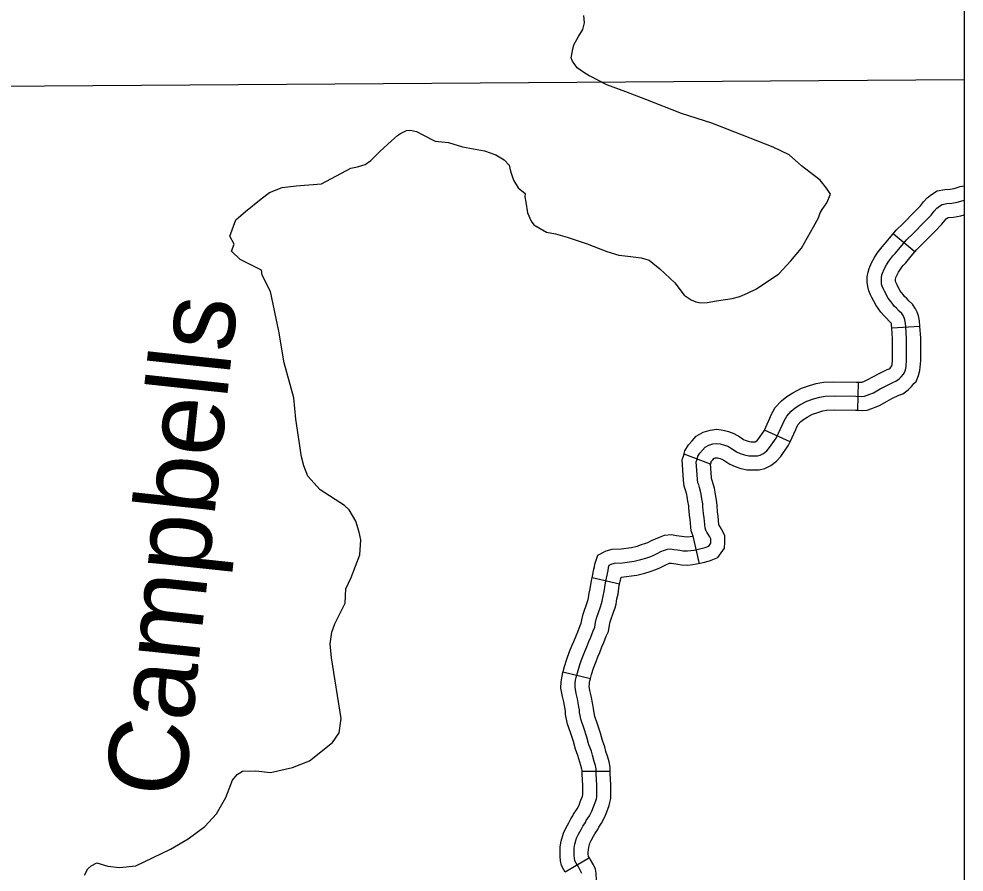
# Model space of a CAD drawing. Extents: x 1377389 to 1380723, y 1168351 to 1170484.
# Drawn here: x 1379747.5 to 1379848, y 1168972.1 to 1169062.8 of the extents above; entities that cross this region are included whole.
import ezdxf

# ---------------------------------------------------------------- set-up
doc = ezdxf.new("R2010")
doc.units = 0
doc.layers.add('B_Fill', color=7, linetype='Continuous')
doc.layers.add('B_Text', color=7, linetype='Continuous')

msp = doc.modelspace()

# ---------------------------------------------------------------- linework, layer by layer
at = {"layer": 'B_Fill'}
for p, q in [((1379842.8, 1169038.05), (1379840.5, 1169039.97)), ((1379843.34, 1169030.11), (1379840.35, 1169029.94)), ((1379836.72, 1169021.19), (1379836.8, 1169024.18)), ((1379829.52, 1169017.83), (1379826.8, 1169019.09)), ((1379821.05, 1169015.47), (1379818.24, 1169016.51)), ((1379819.87, 1169004.87), (1379819.2, 1169007.8)), ((1379811.39, 1169002.71), (1379808.46, 1169003.36)), ((1379808.28, 1168992.64), (1379805.36, 1168993.33)), ((1379810.4, 1168982.75), (1379807.4, 1168982.75)), ((1379808.19, 1168973.58), (1379805.6, 1168972.07))]:
    msp.add_line(p, q, dxfattribs=at)
for points in [[(1379809, 1169056.35), (1379808.4, 1169056.64), (1379808.16, 1169056.75), (1379807.58, 1169057.12), (1379806.89, 1169057.63), (1379806.36, 1169058.32), (1379806.22, 1169058.69), (1379806.36, 1169059.41), (1379806.52, 1169060.07), (1379807.02, 1169060.95), (1379807.47, 1169061.7), (1379807.66, 1169062.41), (1379807.58, 1169063.19)], [(1379745.02, 1169055.65), (1379848.03, 1169056.39)], [(1379782.85, 1169003.41), (1379783.75, 1169005.83), (1379783.85, 1169007.41), (1379783.68, 1169008.24), (1379783.32, 1169009.39), (1379782.61, 1169010.59), (1379782.12, 1169011.05), (1379779.54, 1169012.73), (1379778.23, 1169014.18), (1379777.81, 1169015.28), (1379777.55, 1169016.25), (1379776.96, 1169020.23), (1379776.73, 1169022.53), (1379775.7, 1169026.23), (1379775.13, 1169029.59), (1379774.27, 1169033.82), (1379773.36, 1169035.57), (1379773.3, 1169036.1), (1379771.03, 1169037.23), (1379770.12, 1169038.1), (1379770.39, 1169038.85), (1379769.93, 1169039.72), (1379770.55, 1169041.44), (1379771.6, 1169042.35), (1379773.27, 1169043.69), (1379774.13, 1169044.36), (1379775.48, 1169044.88), (1379777, 1169045.08), (1379779.67, 1169045.27), (1379782.81, 1169046.94), (1379783.5, 1169047.1), (1379784.33, 1169047.34), (1379784.93, 1169047.75), (1379785.87, 1169048.72), (1379787.13, 1169049.86), (1379787.76, 1169050.42), (1379788.09, 1169050.64), (1379788.72, 1169050.94), (1379789.14, 1169050.99), (1379789.77, 1169050.85), (1379790.47, 1169050.5), (1379791.77, 1169049.81), (1379793.19, 1169049.66), (1379794.67, 1169049.22), (1379797.01, 1169048.8), (1379798.21, 1169048.37), (1379799.12, 1169047.82), (1379799.63, 1169047.26), (1379799.79, 1169046.64), (1379800.11, 1169045.66), (1379800.59, 1169044.86), (1379801.33, 1169044.25), (1379801.31, 1169043.9), (1379801.43, 1169043.31), (1379801.6, 1169042.2), (1379801.97, 1169041.3), (1379802.26, 1169040.93), (1379802.95, 1169040.53), (1379803.62, 1169040.15), (1379804.58, 1169039.94), (1379805.8, 1169039.62), (1379807.95, 1169038.88), (1379810.02, 1169038.08), (1379811.32, 1169037.68), (1379812.28, 1169037.58), (1379813.69, 1169037.39), (1379814.54, 1169037.15), (1379814.94, 1169036.83), (1379815.68, 1169036.25), (1379817.25, 1169034.73), (1379818.26, 1169033.43), (1379819, 1169032.92), (1379819.51, 1169032.74), (1379819.99, 1169032.6), (1379820.69, 1169032.67), (1379821.68, 1169032.83), (1379823.36, 1169033.08), (1379824.19, 1169033.29), (1379825.01, 1169033.64), (1379825.94, 1169034.12), (1379828.33, 1169035.71), (1379829.61, 1169037.07), (1379830.74, 1169038.45), (1379832.02, 1169040.69), (1379832.53, 1169041.67), (1379832.74, 1169042.18), (1379832.95, 1169042.55), (1379833.43, 1169043.27), (1379833.83, 1169044.17), (1379833.41, 1169044.81), (1379832.71, 1169045.66), (1379832.13, 1169046.14), (1379830.75, 1169047.2), (1379829.41, 1169048.36), (1379827.73, 1169049.17), (1379821.21, 1169051.72), (1379817.97, 1169052.76), (1379814.17, 1169054.25), (1379812.04, 1169055.05), (1379810.02, 1169055.82), (1379809, 1169056.35)], [(1379840.5, 1169039.97), (1379840.8, 1169040.33), (1379841.54, 1169041.06), (1379842.75, 1169042.29), (1379843.38, 1169042.94), (1379843.7, 1169043.35), (1379844.09, 1169043.77), (1379844.55, 1169044.15), (1379845.18, 1169044.52), (1379846, 1169044.67), (1379846.55, 1169044.7), (1379846.96, 1169044.78), (1379847.6, 1169044.98), (1379848.03, 1169045.05)], [(1379841.81, 1169030.47), (1379841.74, 1169030.81), (1379841.65, 1169031.03), (1379841.55, 1169031.26), (1379841.41, 1169031.49), (1379841.12, 1169031.72), (1379840.86, 1169032.04), (1379840.61, 1169032.27), (1379840.37, 1169032.57), (1379839.95, 1169033.13), (1379839.56, 1169033.85), (1379839.45, 1169034.08), (1379839.33, 1169034.38), (1379839.26, 1169034.62), (1379839.24, 1169034.87), (1379839.24, 1169035.26), (1379839.3, 1169035.58), (1379839.35, 1169035.79), (1379839.52, 1169036.21), (1379839.79, 1169036.67), (1379840.03, 1169037.05), (1379840.23, 1169037.32), (1379840.46, 1169037.6), (1379840.7, 1169037.86), (1379841.27, 1169038.55), (1379841.9, 1169039.31), (1379842.6, 1169039.99), (1379843.83, 1169041.24), (1379844.52, 1169041.96), (1379844.84, 1169042.37), (1379845.12, 1169042.67), (1379845.42, 1169042.91), (1379845.71, 1169043.09), (1379846.19, 1169043.18), (1379846.73, 1169043.21), (1379847.31, 1169043.32), (1379847.95, 1169043.51), (1379848.03, 1169043.53)], [(1379842.8, 1169038.05), (1379843, 1169038.29), (1379843.66, 1169038.93), (1379844.91, 1169040.2), (1379845.66, 1169040.98), (1379845.97, 1169041.39), (1379846.14, 1169041.57), (1379846.26, 1169041.67), (1379846.37, 1169041.69), (1379846.92, 1169041.72), (1379847.67, 1169041.86), (1379848.03, 1169041.97)], [(1379840.35, 1169029.94), (1379840.35, 1169029.94), (1379840.32, 1169030.25), (1379840.3, 1169030.38), (1379840.27, 1169030.45), (1379840.25, 1169030.5), (1379840.07, 1169030.65), (1379839.77, 1169031), (1379839.52, 1169031.24), (1379839.19, 1169031.64), (1379838.68, 1169032.32), (1379838.22, 1169033.18), (1379838.08, 1169033.48), (1379837.91, 1169033.89), (1379837.78, 1169034.36), (1379837.74, 1169034.82), (1379837.74, 1169035.38), (1379837.83, 1169035.88), (1379837.92, 1169036.26), (1379838.18, 1169036.87), (1379838.5, 1169037.44), (1379838.8, 1169037.9), (1379839.04, 1169038.23), (1379839.32, 1169038.58), (1379839.57, 1169038.85), (1379840.11, 1169039.51), (1379840.5, 1169039.97)], [(1379843.34, 1169030.11), (1379843.34, 1169030.15), (1379843.3, 1169030.69), (1379843.18, 1169031.23), (1379843.03, 1169031.62), (1379842.87, 1169031.97), (1379842.55, 1169032.49), (1379842.18, 1169032.79), (1379841.95, 1169033.07), (1379841.71, 1169033.3), (1379841.55, 1169033.49), (1379841.21, 1169033.94), (1379840.9, 1169034.52), (1379840.83, 1169034.68), (1379840.75, 1169034.87), (1379840.75, 1169034.89), (1379840.74, 1169034.92), (1379840.74, 1169035.13), (1379840.77, 1169035.27), (1379840.78, 1169035.31), (1379840.87, 1169035.54), (1379841.07, 1169035.89), (1379841.27, 1169036.21), (1379841.42, 1169036.4), (1379841.59, 1169036.61), (1379841.83, 1169036.88), (1379842.42, 1169037.59), (1379842.8, 1169038.05)], [(1379810.17, 1169004.15), (1379810.21, 1169004.48), (1379810.29, 1169004.73), (1379810.5, 1169004.83), (1379810.83, 1169004.92), (1379811.7, 1169004.96), (1379812.93, 1169005.13), (1379813.65, 1169005.3), (1379814.17, 1169005.47), (1379814.71, 1169005.65), (1379815.04, 1169005.79), (1379815.45, 1169006), (1379815.78, 1169006.15), (1379816.17, 1169006.31), (1379816.5, 1169006.43), (1379816.84, 1169006.46), (1379817.17, 1169006.39), (1379817.54, 1169006.34), (1379817.79, 1169006.31), (1379818.12, 1169006.25), (1379818.6, 1169006.24), (1379818.98, 1169006.27), (1379819.3, 1169006.32), (1379819.65, 1169006.39), (1379820.5, 1169006.59), (1379820.87, 1169006.75), (1379821.08, 1169007.04), (1379821.09, 1169007.24), (1379821.09, 1169007.5), (1379820.99, 1169007.71), (1379820.8, 1169008), (1379820.65, 1169008.24), (1379820.57, 1169008.44), (1379820.48, 1169008.7), (1379820.37, 1169009.76), (1379820.3, 1169010.21), (1379820.25, 1169010.92), (1379820.23, 1169011.23), (1379820.13, 1169011.76), (1379820.06, 1169012.25), (1379820, 1169012.57), (1379819.88, 1169012.98), (1379819.81, 1169013.26), (1379819.72, 1169013.47), (1379819.69, 1169013.87), (1379819.55, 1169015.72), (1379819.67, 1169016.06), (1379819.72, 1169016.32), (1379819.92, 1169016.62), (1379820.2, 1169016.94), (1379820.5, 1169017.25), (1379820.87, 1169017.48), (1379821.31, 1169017.61), (1379821.73, 1169017.66), (1379822.1, 1169017.61), (1379822.54, 1169017.48), (1379822.91, 1169017.36), (1379823.36, 1169017.08), (1379823.84, 1169016.78), (1379824.21, 1169016.6), (1379824.68, 1169016.46), (1379825.14, 1169016.36), (1379825.67, 1169016.34), (1379826.04, 1169016.36), (1379826.35, 1169016.43), (1379826.69, 1169016.58), (1379827.06, 1169016.88), (1379827.35, 1169017.22), (1379828.06, 1169018.24), (1379828.76, 1169019.75), (1379828.88, 1169020.07), (1379829.17, 1169020.58), (1379829.64, 1169021.09), (1379830.06, 1169021.44), (1379830.57, 1169021.76), (1379831.31, 1169022.16), (1379832.03, 1169022.39), (1379832.67, 1169022.59), (1379833.25, 1169022.69), (1379834.2, 1169022.73), (1379836.52, 1169022.69), (1379837.15, 1169022.67), (1379837.43, 1169022.69), (1379837.71, 1169022.78), (1379838.01, 1169022.9), (1379838.4, 1169023.06), (1379839.12, 1169023.47), (1379839.68, 1169023.77), (1379840.47, 1169024.15), (1379840.77, 1169024.28), (1379841.12, 1169024.52), (1379841.35, 1169024.75), (1379841.58, 1169025.03), (1379841.67, 1169025.12), (1379841.78, 1169025.37), (1379841.85, 1169025.65), (1379841.86, 1169025.88), (1379841.92, 1169026.53), (1379841.92, 1169028.83), (1379841.85, 1169030.05), (1379841.81, 1169030.47)], [(1379836.72, 1169021.19), (1379837.18, 1169021.17), (1379837.71, 1169021.21), (1379838.22, 1169021.37), (1379838.58, 1169021.52), (1379839.05, 1169021.71), (1379839.84, 1169022.15), (1379840.36, 1169022.43), (1379841.09, 1169022.78), (1379841.5, 1169022.95), (1379842.09, 1169023.37), (1379842.47, 1169023.75), (1379842.7, 1169024.03), (1379842.93, 1169024.26), (1379843.2, 1169024.89), (1379843.33, 1169025.41), (1379843.36, 1169025.76), (1379843.42, 1169026.47), (1379843.42, 1169028.88), (1379843.34, 1169030.11)], [(1379836.8, 1169024.18), (1379837.12, 1169024.18), (1379837.16, 1169024.18), (1379837.2, 1169024.19), (1379837.44, 1169024.29), (1379837.74, 1169024.41), (1379838.4, 1169024.78), (1379839, 1169025.1), (1379839.86, 1169025.52), (1379840.05, 1169025.6), (1379840.16, 1169025.68), (1379840.24, 1169025.76), (1379840.36, 1169025.91), (1379840.37, 1169026), (1379840.42, 1169026.59), (1379840.42, 1169028.79), (1379840.35, 1169029.94)], [(1379826.8, 1169019.09), (1379827.38, 1169020.34), (1379827.52, 1169020.71), (1379827.94, 1169021.47), (1379828.61, 1169022.18), (1379829.18, 1169022.66), (1379829.82, 1169023.05), (1379830.72, 1169023.55), (1379831.59, 1169023.82), (1379832.31, 1169024.05), (1379833.08, 1169024.19), (1379834.18, 1169024.23), (1379836.55, 1169024.19), (1379836.8, 1169024.18)], [(1379829.52, 1169017.83), (1379830.14, 1169019.16), (1379830.25, 1169019.43), (1379830.39, 1169019.69), (1379830.67, 1169020), (1379830.94, 1169020.22), (1379831.33, 1169020.46), (1379831.9, 1169020.78), (1379832.48, 1169020.96), (1379833.02, 1169021.13), (1379833.41, 1169021.2), (1379834.21, 1169021.23), (1379836.48, 1169021.19), (1379836.72, 1169021.19)], [(1379818.22, 1169016.46), (1379818.31, 1169016.89), (1379818.72, 1169017.53), (1379819.09, 1169017.95), (1379819.54, 1169018.42), (1379820.26, 1169018.87), (1379821.01, 1169019.08), (1379821.74, 1169019.17), (1379822.41, 1169019.08), (1379822.98, 1169018.92), (1379823.54, 1169018.73), (1379824.16, 1169018.35), (1379824.56, 1169018.09), (1379824.75, 1169018.01), (1379825.06, 1169017.91), (1379825.33, 1169017.85), (1379825.66, 1169017.84), (1379825.84, 1169017.85), (1379825.86, 1169017.85), (1379825.88, 1169017.86), (1379826.02, 1169017.97), (1379826.17, 1169018.15), (1379826.75, 1169018.99), (1379826.8, 1169019.09)], [(1379821.05, 1169015.47), (1379821.12, 1169015.65), (1379821.14, 1169015.73), (1379821.3, 1169015.92), (1379821.45, 1169016.08), (1379821.48, 1169016.09), (1379821.6, 1169016.13), (1379821.71, 1169016.14), (1379821.79, 1169016.13), (1379822.1, 1169016.05), (1379822.27, 1169015.99), (1379822.57, 1169015.8), (1379823.11, 1169015.46), (1379823.67, 1169015.2), (1379824.3, 1169015.01), (1379824.94, 1169014.86), (1379825.68, 1169014.84), (1379826.24, 1169014.86), (1379826.84, 1169015), (1379827.49, 1169015.31), (1379828.09, 1169015.79), (1379828.54, 1169016.29), (1379829.37, 1169017.49), (1379829.52, 1169017.83)], [(1379819.2, 1169007.8), (1379819, 1169008.38), (1379818.88, 1169009.57), (1379818.81, 1169010.04), (1379818.75, 1169010.82), (1379818.74, 1169011.04), (1379818.65, 1169011.51), (1379818.57, 1169012.03), (1379818.54, 1169012.23), (1379818.43, 1169012.58), (1379818.38, 1169012.79), (1379818.25, 1169013.11), (1379818.19, 1169013.75), (1379818.03, 1169015.93), (1379818.24, 1169016.51)], [(1379820.26, 1169004.99), (1379820.96, 1169005.16), (1379821.85, 1169005.53), (1379822.53, 1169006.51), (1379822.59, 1169007.17), (1379822.59, 1169007.86), (1379822.28, 1169008.48), (1379822.07, 1169008.79), (1379821.99, 1169008.93), (1379821.97, 1169008.98), (1379821.95, 1169009.01), (1379821.86, 1169009.94), (1379821.79, 1169010.38), (1379821.75, 1169011.01), (1379821.72, 1169011.42), (1379821.61, 1169012.01), (1379821.54, 1169012.48), (1379821.47, 1169012.91), (1379821.33, 1169013.38), (1379821.24, 1169013.73), (1379821.2, 1169013.83), (1379821.18, 1169014), (1379821.07, 1169015.51), (1379821.05, 1169015.47)], [(1379808.68, 1169004.33), (1379808.74, 1169004.81), (1379809.06, 1169005.79), (1379809.97, 1169006.25), (1379810.61, 1169006.41), (1379811.57, 1169006.45), (1379812.65, 1169006.6), (1379813.24, 1169006.75), (1379813.71, 1169006.9), (1379814.18, 1169007.05), (1379814.4, 1169007.14), (1379814.79, 1169007.35), (1379815.2, 1169007.53), (1379815.63, 1169007.7), (1379816.16, 1169007.9), (1379816.92, 1169007.98), (1379817.43, 1169007.87), (1379818.01, 1169007.79), (1379818.27, 1169007.75), (1379818.56, 1169007.74), (1379819.2, 1169007.8)], [(1379811.54, 1169003.42), (1379813.21, 1169003.65), (1379814.06, 1169003.86), (1379814.63, 1169004.04), (1379815.23, 1169004.24), (1379815.68, 1169004.43), (1379816.1, 1169004.65), (1379816.37, 1169004.77), (1379816.71, 1169004.91), (1379816.8, 1169004.94), (1379816.91, 1169004.92), (1379817.57, 1169004.82), (1379817.98, 1169004.76), (1379818.64, 1169004.73), (1379819.18, 1169004.78), (1379819.57, 1169004.85), (1379819.97, 1169004.93), (1379820.26, 1169004.99)], [(1379807.38, 1168971.91), (1379807.27, 1168972.14), (1379806.97, 1168972.69), (1379806.78, 1168973.02), (1379806.64, 1168973.28), (1379806.59, 1168973.54), (1379806.55, 1168973.82), (1379806.55, 1168974.19), (1379806.57, 1168974.6), (1379806.64, 1168975.02), (1379806.82, 1168975.68), (1379807.02, 1168976.11), (1379807.3, 1168976.59), (1379807.47, 1168976.94), (1379807.76, 1168977.33), (1379807.84, 1168977.54), (1379808.17, 1168978.04), (1379808.44, 1168978.55), (1379808.62, 1168979.02), (1379808.85, 1168979.64), (1379808.92, 1168979.86), (1379808.97, 1168980.08), (1379808.97, 1168980.52), (1379808.96, 1168981.31), (1379808.9, 1168982.52), (1379808.9, 1168983.05), (1379808.82, 1168983.42), (1379808.69, 1168983.84), (1379808.49, 1168984.51), (1379808.39, 1168984.92), (1379808.13, 1168985.62), (1379807.91, 1168986.41), (1379807.58, 1168987.4), (1379807.3, 1168988.21), (1379807.13, 1168989.03), (1379807.12, 1168989.31), (1379807.06, 1168989.65), (1379806.91, 1168990.48), (1379806.76, 1168991.06), (1379806.66, 1168991.74), (1379806.67, 1168992.17), (1379806.71, 1168992.49), (1379806.76, 1168992.75), (1379806.83, 1168993.03), (1379806.97, 1168993.52), (1379807.2, 1168994.25), (1379807.47, 1168995), (1379807.68, 1168995.54), (1379807.9, 1168996.02), (1379808.13, 1168996.59), (1379808.33, 1168997.06), (1379808.58, 1168997.72), (1379808.75, 1168998.11), (1379808.84, 1168998.62), (1379808.94, 1168999.09), (1379809.35, 1169000.29), (1379809.46, 1169000.63), (1379809.54, 1169000.9), (1379809.63, 1169001.43), (1379809.75, 1169001.93), (1379809.88, 1169002.83), (1379810.17, 1169004.15)], [(1379808.46, 1169003.36), (1379808.7, 1169004.47)], [(1379754.45, 1168971.73), (1379754.83, 1168972.41), (1379755.16, 1168972.73), (1379755.79, 1168973.05), (1379756.96, 1168972.71), (1379758.19, 1168972.56), (1379759.92, 1168972.73), (1379763.6, 1168974.5), (1379765.5, 1168975.62), (1379767.26, 1168976.91), (1379768.51, 1168978.28), (1379769.5, 1168980.01), (1379770.2, 1168981.83), (1379770.7, 1168982.45), (1379771.29, 1168982.79), (1379772.69, 1168982.83), (1379774.27, 1168982.65), (1379776.6, 1168983.2), (1379778.4, 1168983.91), (1379780.85, 1168985.85), (1379781.56, 1168986.87), (1379781.77, 1168988.41), (1379780.75, 1168994.87), (1379780.61, 1168996.36), (1379780.79, 1168997.59), (1379781.08, 1168998.46), (1379782.2, 1169000.67), (1379782.25, 1169002.21), (1379782.85, 1169003.41)], [(1379805.36, 1168993.33), (1379805.38, 1168993.41), (1379805.53, 1168993.95), (1379805.78, 1168994.73), (1379806.07, 1168995.52), (1379806.29, 1168996.12), (1379806.52, 1168996.61), (1379806.75, 1168997.18), (1379806.94, 1168997.62), (1379807.19, 1168998.3), (1379807.3, 1168998.55), (1379807.36, 1168998.91), (1379807.5, 1168999.5), (1379807.93, 1169000.76), (1379808.03, 1169001.07), (1379808.08, 1169001.23), (1379808.15, 1169001.73), (1379808.27, 1169002.21), (1379808.4, 1169003.1), (1379808.46, 1169003.36)], [(1379808.28, 1168992.64), (1379808.29, 1168992.66), (1379808.41, 1168993.1), (1379808.62, 1168993.76), (1379808.88, 1168994.48), (1379809.06, 1168994.97), (1379809.27, 1168995.43), (1379809.51, 1168996.01), (1379809.72, 1168996.49), (1379809.96, 1168997.15), (1379810.2, 1168997.67), (1379810.31, 1168998.34), (1379810.39, 1168998.67), (1379810.78, 1168999.82), (1379810.9, 1169000.19), (1379811.01, 1169000.57), (1379811.1, 1169001.14), (1379811.22, 1169001.64), (1379811.35, 1169002.57), (1379811.39, 1169002.71)], [(1379811.39, 1169002.71), (1379811.54, 1169003.42)], [(1379807.4, 1168982.75), (1379807.4, 1168982.89), (1379807.37, 1168983.03), (1379807.25, 1168983.41), (1379807.05, 1168984.11), (1379806.95, 1168984.47), (1379806.7, 1168985.15), (1379806.47, 1168985.97), (1379806.16, 1168986.92), (1379805.85, 1168987.81), (1379805.64, 1168988.84), (1379805.62, 1168989.16), (1379805.59, 1168989.4), (1379805.45, 1168990.16), (1379805.3, 1168990.75), (1379805.15, 1168991.64), (1379805.17, 1168992.3), (1379805.23, 1168992.74), (1379805.3, 1168993.08), (1379805.36, 1168993.33)], [(1379810.4, 1168982.75), (1379810.4, 1168983.22), (1379810.27, 1168983.81), (1379810.12, 1168984.28), (1379809.94, 1168984.91), (1379809.82, 1168985.38), (1379809.56, 1168986.08), (1379809.35, 1168986.84), (1379809, 1168987.89), (1379808.75, 1168988.61), (1379808.63, 1168989.21), (1379808.61, 1168989.47), (1379808.54, 1168989.9), (1379808.38, 1168990.81), (1379808.23, 1168991.37), (1379808.16, 1168991.83), (1379808.17, 1168992.05), (1379808.19, 1168992.24), (1379808.23, 1168992.42), (1379808.28, 1168992.64)], [(1379805.6, 1168972.07), (1379805.47, 1168972.29), (1379805.22, 1168972.76), (1379805.11, 1168973.27), (1379805.05, 1168973.72), (1379805.05, 1168974.24), (1379805.08, 1168974.77), (1379805.17, 1168975.34), (1379805.41, 1168976.19), (1379805.69, 1168976.8), (1379805.97, 1168977.3), (1379806.19, 1168977.74), (1379806.43, 1168978.05), (1379806.5, 1168978.23), (1379806.88, 1168978.8), (1379807.07, 1168979.17), (1379807.21, 1168979.54), (1379807.43, 1168980.13), (1379807.47, 1168980.27), (1379807.47, 1168980.5), (1379807.46, 1168981.26), (1379807.4, 1168982.49), (1379807.4, 1168982.75)], [(1379808.19, 1168973.58), (1379808.09, 1168973.74), (1379808.07, 1168973.79), (1379808.07, 1168973.8), (1379808.05, 1168973.93), (1379808.05, 1168974.14), (1379808.07, 1168974.43), (1379808.11, 1168974.71), (1379808.23, 1168975.16), (1379808.36, 1168975.42), (1379808.62, 1168975.88), (1379808.75, 1168976.15), (1379809.09, 1168976.6), (1379809.19, 1168976.86), (1379809.46, 1168977.27), (1379809.81, 1168977.93), (1379810.02, 1168978.49), (1379810.27, 1168979.16), (1379810.36, 1168979.46), (1379810.47, 1168979.9), (1379810.47, 1168980.53), (1379810.46, 1168981.35), (1379810.4, 1168982.55), (1379810.4, 1168982.75)], [(1379812.59, 1168964.46), (1379812.55, 1168964.51), (1379812.13, 1168965.05), (1379811.74, 1168965.53), (1379811.34, 1168966.02), (1379810.35, 1168967.41), (1379809.63, 1168968.32), (1379809.38, 1168968.7), (1379809.24, 1168968.98), (1379809.11, 1168969.32), (1379809.05, 1168969.51), (1379808.98, 1168970.47), (1379808.94, 1168971.37), (1379808.91, 1168971.73), (1379808.89, 1168971.94), (1379808.82, 1168972.36), (1379808.61, 1168972.83), (1379808.27, 1168973.43), (1379808.19, 1168973.58)]]:
    msp.add_lwpolyline(points, dxfattribs=at)
at = {"layer": 'B_Text'}
msp.add_lwpolyline([(1378340.61, 1169579.43), (1379848.03, 1169579.43), (1379848.03, 1168702.1), (1378340.61, 1168702.1)], close=True, dxfattribs=at)

# ---------------------------------------------------------------- texts
at = {"layer": 'B_Fill'}
msp.add_text('Campbells', height=8.448, rotation=83.8586, dxfattribs=at).set_placement((1379765.04, 1168979.82))

doc.saveas('drawing.dxf')
